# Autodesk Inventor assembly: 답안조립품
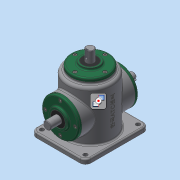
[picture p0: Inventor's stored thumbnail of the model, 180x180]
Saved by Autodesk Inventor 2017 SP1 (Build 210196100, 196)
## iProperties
Part Number: 답안조립품
Material: 일반
Document SubType Name: Assembly
Designer: MRC
Author: MRC
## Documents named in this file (16)
- C:\Users\MRC\Desktop\710116V1006\답안조립품.iam
- C:\Users\MRC\Desktop\710116V1006\본체.ipt
- C:\Users\MRC\Desktop\710116V1006\메인 베벨기어.ipt
- C:\Users\MRC\Desktop\710116V1006\메인 축.ipt
- 메인 축.ipt
- C:\Users\MRC\Desktop\710116V1006\베어링 6203.ipt
- C:\Users\MRC\Desktop\710116V1006\볼트 M4.ipt
- 볼트 M4.ipt
- C:\Users\MRC\Desktop\710116V1006\서브 베벨기어.ipt
- C:\Users\MRC\Desktop\710116V1006\서브 축.ipt
- 서브 축.ipt
- C:\Users\MRC\Desktop\710116V1006\오일 실.ipt
- 오일 실.ipt
- C:\Users\MRC\Desktop\710116V1006\커버.ipt
- C:\Users\MRC\Desktop\710116V1006\키 4x4.ipt
- C:\Users\MRC\Desktop\710116V1006\키 5x5.ipt
